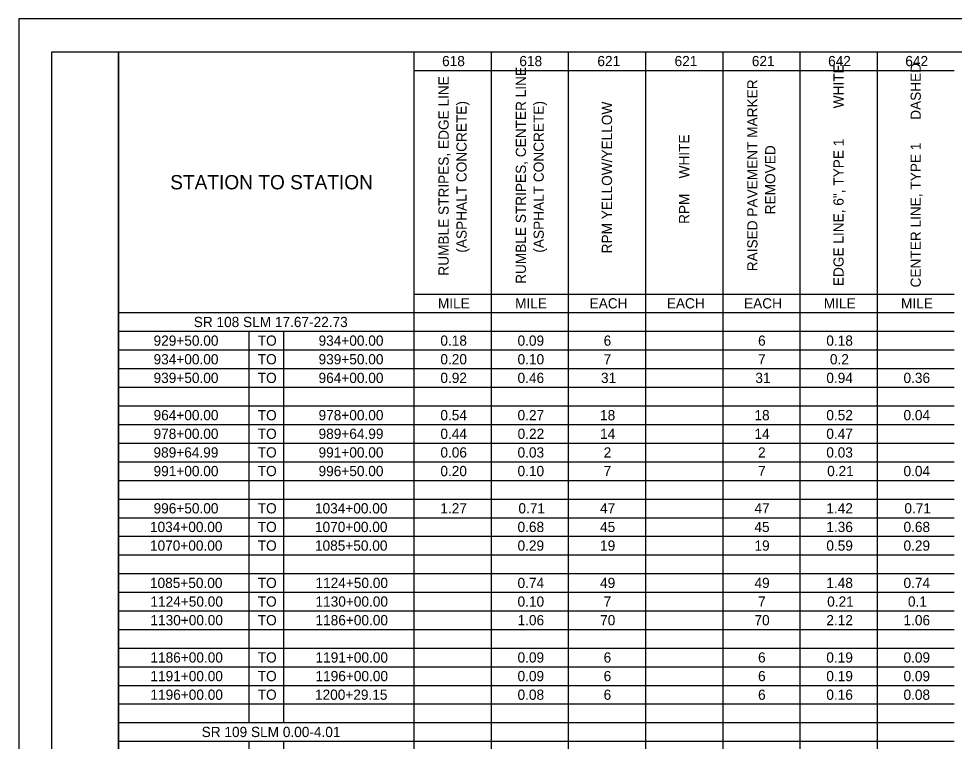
# Model space of a CAD drawing. Extents: x 0 to 34, y 0 to 22.
# Drawn here: x 0 to 14.06, y 11.14 to 22 of the extents above; entities that cross this region are included whole.
import ezdxf

# ---------------------------------------------------------------- set-up
doc = ezdxf.new("R2010")
doc.units = 0
for name, color, linetype in [('SH_Border', 7, 'Continuous'), ('SH_Cut_Line', 7, 'Continuous'), ('SH_Text', 7, 'Continuous')]:
    doc.layers.add(name, color=color, linetype=linetype)

msp = doc.modelspace()

# ---------------------------------------------------------------- linework, layer by layer
at = {"layer": 'SH_Border'}
for points in [[(0.5, 21.5), (1.5, 21.5), (1.5, 0.5), (0.5, 0.5)], [(1.5, 21.5), (33.5, 21.5), (33.5, 0.5), (1.5, 0.5)]]:
    msp.add_lwpolyline(points, close=True, dxfattribs=at)
at = {"layer": 'SH_Cut_Line'}
msp.add_lwpolyline([(0, 0), (34, 0), (34, 22), (0, 22)], close=True, dxfattribs=at)
at = {"layer": 'SH_Text'}
for p, q in [((1.5, 21.504), (3.02, 21.504)), ((1.5, 21.504), (1.5, 21.223)), ((3.02, 21.504), (14.062, 21.504)), ((5.941, 21.504), (5.941, 21.223)), ((7.101, 21.504), (7.101, 21.223)), ((8.261, 21.504), (8.261, 21.223)), ((9.421, 21.504), (9.421, 21.223)), ((10.582, 21.504), (10.582, 21.223)), ((11.742, 21.504), (11.742, 21.223)), ((12.902, 21.504), (12.902, 21.223)), ((1.5, 21.223), (1.5, 20.943)), ((5.941, 21.223), (14.062, 21.223)), ((5.941, 21.223), (5.941, 20.943)), ((7.101, 21.223), (7.101, 20.943)), ((8.261, 21.223), (8.261, 20.943)), ((9.421, 21.223), (9.421, 20.943)), ((10.582, 21.223), (10.582, 20.943)), ((11.742, 21.223), (11.742, 20.943)), ((12.902, 21.223), (12.902, 20.943)), ((1.5, 20.943), (1.5, 20.663)), ((5.941, 20.943), (5.941, 20.663)), ((7.101, 20.943), (7.101, 20.663)), ((8.261, 20.943), (8.261, 20.663)), ((9.421, 20.943), (9.421, 20.663)), ((10.582, 20.943), (10.582, 20.663)), ((11.742, 20.943), (11.742, 20.663)), ((12.902, 20.943), (12.902, 20.663)), ((1.5, 20.663), (1.5, 20.383)), ((5.941, 20.663), (5.941, 20.383)), ((7.101, 20.663), (7.101, 20.383)), ((8.261, 20.663), (8.261, 20.383)), ((9.421, 20.663), (9.421, 20.383)), ((10.582, 20.663), (10.582, 20.383)), ((11.742, 20.663), (11.742, 20.383)), ((12.902, 20.663), (12.902, 20.383)), ((1.5, 20.383), (1.5, 20.103)), ((5.941, 20.383), (5.941, 20.103)), ((7.101, 20.383), (7.101, 20.103)), ((8.261, 20.383), (8.261, 20.103)), ((9.421, 20.383), (9.421, 20.103)), ((10.582, 20.383), (10.582, 20.103)), ((11.742, 20.383), (11.742, 20.103)), ((12.902, 20.383), (12.902, 20.103)), ((1.5, 20.103), (1.5, 19.823)), ((5.941, 20.103), (5.941, 19.823)), ((7.101, 20.103), (7.101, 19.823)), ((8.261, 20.103), (8.261, 19.823)), ((9.421, 20.103), (9.421, 19.823)), ((10.582, 20.103), (10.582, 19.823)), ((11.742, 20.103), (11.742, 19.823)), ((12.902, 20.103), (12.902, 19.823)), ((1.5, 19.823), (1.5, 19.543)), ((5.941, 19.823), (5.941, 19.543)), ((7.101, 19.823), (7.101, 19.543)), ((8.261, 19.823), (8.261, 19.543)), ((9.421, 19.823), (9.421, 19.543)), ((10.582, 19.823), (10.582, 19.543)), ((11.742, 19.823), (11.742, 19.543)), ((12.902, 19.823), (12.902, 19.543)), ((1.5, 19.543), (1.5, 18.983)), ((5.941, 19.543), (5.941, 18.983)), ((7.101, 19.543), (7.101, 18.983)), ((8.261, 19.543), (8.261, 18.983)), ((9.421, 19.543), (9.421, 18.983)), ((10.582, 19.543), (10.582, 18.983)), ((11.742, 19.543), (11.742, 18.983)), ((12.902, 19.543), (12.902, 18.983)), ((1.5, 18.983), (1.5, 18.143)), ((5.941, 18.983), (5.941, 18.143)), ((7.101, 18.983), (7.101, 18.143)), ((8.261, 18.983), (8.261, 18.143)), ((9.421, 18.983), (9.421, 18.143)), ((10.582, 18.983), (10.582, 18.143)), ((11.742, 18.983), (11.742, 18.143)), ((12.902, 18.983), (12.902, 18.143)), ((1.5, 18.143), (1.5, 17.863)), ((5.941, 18.143), (5.941, 17.863)), ((7.101, 18.143), (7.101, 17.863)), ((8.261, 18.143), (8.261, 17.863)), ((9.421, 18.143), (9.421, 17.863)), ((10.582, 18.143), (10.582, 17.863)), ((11.742, 18.143), (11.742, 17.863)), ((12.902, 18.143), (12.902, 17.863)), ((1.5, 17.863), (1.5, 17.303)), ((5.941, 17.863), (14.062, 17.863)), ((5.941, 17.863), (5.941, 17.303)), ((7.101, 17.863), (7.101, 17.303)), ((8.261, 17.863), (8.261, 17.303)), ((9.421, 17.863), (9.421, 17.303)), ((10.582, 17.863), (10.582, 17.303)), ((11.742, 17.863), (11.742, 17.303)), ((12.902, 17.863), (12.902, 17.303)), ((1.5, 17.583), (3.02, 17.583)), ((3.02, 17.583), (14.062, 17.583)), ((1.5, 17.303), (3.02, 17.303)), ((1.5, 17.303), (1.5, 17.023)), ((3.02, 17.303), (14.062, 17.303)), ((3.46, 17.303), (3.46, 17.023)), ((3.98, 17.303), (3.98, 17.023)), ((5.941, 17.303), (5.941, 17.023)), ((7.101, 17.303), (7.101, 17.023)), ((8.261, 17.303), (8.261, 17.023)), ((9.421, 17.303), (9.421, 17.023)), ((10.582, 17.303), (10.582, 17.023)), ((11.742, 17.303), (11.742, 17.023)), ((12.902, 17.303), (12.902, 17.023)), ((1.5, 17.023), (3.02, 17.023)), ((1.5, 17.023), (1.5, 15.903)), ((3.02, 17.023), (14.062, 17.023)), ((3.46, 17.023), (3.46, 15.903)), ((3.98, 17.023), (3.98, 15.903)), ((5.941, 17.023), (5.941, 15.903)), ((7.101, 17.023), (7.101, 15.903)), ((8.261, 17.023), (8.261, 15.903)), ((9.421, 17.023), (9.421, 15.903)), ((10.582, 17.023), (10.582, 15.903)), ((11.742, 17.023), (11.742, 15.903)), ((12.902, 17.023), (12.902, 15.903)), ((1.5, 16.743), (3.02, 16.743)), ((3.02, 16.743), (14.062, 16.743)), ((1.5, 16.463), (3.02, 16.463)), ((3.02, 16.463), (14.062, 16.463)), ((1.5, 16.183), (3.02, 16.183)), ((3.02, 16.183), (14.062, 16.183)), ((1.5, 15.903), (3.02, 15.903)), ((1.5, 15.903), (1.5, 15.622)), ((3.02, 15.903), (14.062, 15.903)), ((3.46, 15.903), (3.46, 15.622)), ((3.98, 15.903), (3.98, 15.622)), ((5.941, 15.903), (5.941, 15.622)), ((7.101, 15.903), (7.101, 15.622)), ((8.261, 15.903), (8.261, 15.622)), ((9.421, 15.903), (9.421, 15.622)), ((10.582, 15.903), (10.582, 15.622)), ((11.742, 15.903), (11.742, 15.622)), ((12.902, 15.903), (12.902, 15.622)), ((1.5, 15.622), (3.02, 15.622)), ((1.5, 15.622), (1.5, 15.062)), ((3.02, 15.622), (14.062, 15.622)), ((3.46, 15.622), (3.46, 15.062)), ((3.98, 15.622), (3.98, 15.062)), ((5.941, 15.622), (5.941, 15.062)), ((7.101, 15.622), (7.101, 15.062)), ((8.261, 15.622), (8.261, 15.062)), ((9.421, 15.622), (9.421, 15.062)), ((10.582, 15.622), (10.582, 15.062)), ((11.742, 15.622), (11.742, 15.062)), ((12.902, 15.622), (12.902, 15.062)), ((1.5, 15.342), (3.02, 15.342)), ((3.02, 15.342), (14.062, 15.342)), ((1.5, 15.062), (3.02, 15.062)), ((1.5, 15.062), (1.5, 14.502)), ((3.02, 15.062), (14.062, 15.062)), ((3.46, 15.062), (3.46, 14.502)), ((3.98, 15.062), (3.98, 14.502)), ((5.941, 15.062), (5.941, 14.502)), ((7.101, 15.062), (7.101, 14.502)), ((8.261, 15.062), (8.261, 14.502)), ((9.421, 15.062), (9.421, 14.502)), ((10.582, 15.062), (10.582, 14.502)), ((11.742, 15.062), (11.742, 14.502)), ((12.902, 15.062), (12.902, 14.502)), ((1.5, 14.782), (3.02, 14.782)), ((3.02, 14.782), (14.062, 14.782)), ((1.5, 14.502), (3.02, 14.502)), ((1.5, 14.502), (1.5, 14.222)), ((3.02, 14.502), (14.062, 14.502)), ((3.46, 14.502), (3.46, 14.222)), ((3.98, 14.502), (3.98, 14.222)), ((5.941, 14.502), (5.941, 14.222)), ((7.101, 14.502), (7.101, 14.222)), ((8.261, 14.502), (8.261, 14.222)), ((9.421, 14.502), (9.421, 14.222)), ((10.582, 14.502), (10.582, 14.222)), ((11.742, 14.502), (11.742, 14.222)), ((12.902, 14.502), (12.902, 14.222)), ((1.5, 14.222), (3.02, 14.222)), ((1.5, 14.222), (1.5, 13.662)), ((3.02, 14.222), (14.062, 14.222)), ((3.46, 14.222), (3.46, 13.662)), ((3.98, 14.222), (3.98, 13.662)), ((5.941, 14.222), (5.941, 13.662)), ((7.101, 14.222), (7.101, 13.662)), ((8.261, 14.222), (8.261, 13.662)), ((9.421, 14.222), (9.421, 13.662)), ((10.582, 14.222), (10.582, 13.662)), ((11.742, 14.222), (11.742, 13.662)), ((12.902, 14.222), (12.902, 13.662)), ((1.5, 13.942), (3.02, 13.942)), ((3.02, 13.942), (14.062, 13.942)), ((1.5, 13.662), (3.02, 13.662)), ((1.5, 13.662), (1.5, 13.382)), ((3.02, 13.662), (14.062, 13.662)), ((3.46, 13.662), (3.46, 13.382)), ((3.98, 13.662), (3.98, 13.382)), ((5.941, 13.662), (5.941, 13.382)), ((7.101, 13.662), (7.101, 13.382)), ((8.261, 13.662), (8.261, 13.382)), ((9.421, 13.662), (9.421, 13.382)), ((10.582, 13.662), (10.582, 13.382)), ((11.742, 13.662), (11.742, 13.382)), ((12.902, 13.662), (12.902, 13.382)), ((1.5, 13.382), (3.02, 13.382)), ((1.5, 13.382), (1.5, 12.542)), ((3.02, 13.382), (14.062, 13.382)), ((3.46, 13.382), (3.46, 12.542)), ((3.98, 13.382), (3.98, 12.542)), ((5.941, 13.382), (5.941, 12.542)), ((7.101, 13.382), (7.101, 12.542)), ((8.261, 13.382), (8.261, 12.542)), ((9.421, 13.382), (9.421, 12.542)), ((10.582, 13.382), (10.582, 12.542)), ((11.742, 13.382), (11.742, 12.542)), ((12.902, 13.382), (12.902, 12.542)), ((1.5, 13.102), (3.02, 13.102)), ((3.02, 13.102), (14.062, 13.102)), ((1.5, 12.822), (3.02, 12.822)), ((3.02, 12.822), (14.062, 12.822)), ((1.5, 12.542), (3.02, 12.542)), ((1.5, 12.542), (1.5, 11.982)), ((3.02, 12.542), (14.062, 12.542)), ((3.46, 12.542), (3.46, 11.982)), ((3.98, 12.542), (3.98, 11.982)), ((5.941, 12.542), (5.941, 11.982)), ((7.101, 12.542), (7.101, 11.982)), ((8.261, 12.542), (8.261, 11.982)), ((9.421, 12.542), (9.421, 11.982)), ((10.582, 12.542), (10.582, 11.982)), ((11.742, 12.542), (11.742, 11.982)), ((12.902, 12.542), (12.902, 11.982)), ((1.5, 12.262), (3.02, 12.262)), ((3.02, 12.262), (14.062, 12.262)), ((1.5, 11.982), (3.02, 11.982)), ((1.5, 11.982), (1.5, 11.142)), ((3.02, 11.982), (14.062, 11.982)), ((3.46, 11.982), (3.46, 11.422)), ((3.98, 11.982), (3.98, 11.422)), ((5.941, 11.982), (5.941, 11.142)), ((7.101, 11.982), (7.101, 11.142)), ((8.261, 11.982), (8.261, 11.142)), ((9.421, 11.982), (9.421, 11.142)), ((10.582, 11.982), (10.582, 11.142)), ((11.742, 11.982), (11.742, 11.142)), ((12.902, 11.982), (12.902, 11.142)), ((1.5, 11.702), (3.02, 11.702)), ((3.02, 11.702), (14.062, 11.702)), ((1.5, 11.422), (3.02, 11.422)), ((3.02, 11.422), (14.062, 11.422)), ((1.5, 11.142), (3.02, 11.142)), ((1.5, 11.142), (1.5, 10.582)), ((3.02, 11.142), (14.062, 11.142)), ((3.46, 11.142), (3.46, 10.582)), ((3.98, 11.142), (3.98, 10.582)), ((5.941, 11.142), (5.941, 10.582)), ((7.101, 11.142), (7.101, 10.582)), ((8.261, 11.142), (8.261, 10.582)), ((9.421, 11.142), (9.421, 10.582)), ((10.582, 11.142), (10.582, 10.582)), ((11.742, 11.142), (11.742, 10.582)), ((12.902, 11.142), (12.902, 10.582))]:
    msp.add_line(p, q, dxfattribs=at)

# ---------------------------------------------------------------- texts
for s, height, p in [('618', 0.1534, (6.364, 21.287)), ('618', 0.1534, (7.525, 21.287)), ('621', 0.1534, (8.698, 21.287)), ('621', 0.1534, (9.858, 21.287)), ('621', 0.1534, (11.019, 21.287)), ('642', 0.1534, (12.166, 21.287)), ('642', 0.1534, (13.326, 21.287)), ('STATION TO STATION', 0.21471, (2.277, 19.436)), ('MILE', 0.1534, (6.301, 17.646)), ('MILE', 0.1534, (7.461, 17.646)), ('EACH', 0.1534, (8.581, 17.646)), ('EACH', 0.1534, (9.741, 17.646)), ('EACH', 0.1534, (10.902, 17.646)), ('MILE', 0.1534, (12.102, 17.646)), ('MILE', 0.1534, (13.262, 17.646)), ('SR 108 SLM 17.67-22.73', 0.15336, (2.631, 17.366)), ('929+50.00', 0.1534, (2.027, 17.086)), ('TO', 0.1534, (3.593, 17.086)), ('934+00.00', 0.1534, (4.507, 17.086)), ('0.18', 0.1534, (6.338, 17.086)), ('0.09', 0.1534, (7.498, 17.086)), ('6', 0.153, (8.792, 17.086)), ('6', 0.153, (11.113, 17.086)), ('0.18', 0.1534, (12.139, 17.086)), ('934+00.00', 0.1534, (2.027, 16.806)), ('TO', 0.1534, (3.593, 16.806)), ('939+50.00', 0.1534, (4.507, 16.806)), ('0.20', 0.1534, (6.338, 16.806)), ('0.10', 0.1534, (7.498, 16.806)), ('7', 0.153, (8.792, 16.806)), ('7', 0.153, (11.113, 16.806)), ('0.2', 0.1534, (12.193, 16.806)), ('939+50.00', 0.1534, (2.027, 16.526)), ('TO', 0.1534, (3.593, 16.526)), ('964+00.00', 0.1534, (4.507, 16.526)), ('0.92', 0.1534, (6.338, 16.526)), ('0.46', 0.1534, (7.498, 16.526)), ('31', 0.1534, (8.752, 16.526)), ('31', 0.1534, (11.072, 16.526)), ('0.94', 0.1534, (12.139, 16.526)), ('0.36', 0.1534, (13.299, 16.526)), ('964+00.00', 0.1534, (2.027, 15.966)), ('TO', 0.1534, (3.593, 15.966)), ('978+00.00', 0.1534, (4.507, 15.966)), ('0.54', 0.1534, (6.338, 15.966)), ('0.27', 0.1534, (7.498, 15.966)), ('18', 0.1534, (8.738, 15.966)), ('18', 0.1534, (11.059, 15.966)), ('0.52', 0.1534, (12.139, 15.966)), ('0.04', 0.1534, (13.299, 15.966)), ('978+00.00', 0.1534, (2.027, 15.686)), ('TO', 0.1534, (3.593, 15.686)), ('989+64.99', 0.1534, (4.507, 15.686)), ('0.44', 0.1534, (6.338, 15.686)), ('0.22', 0.1534, (7.499, 15.686)), ('14', 0.1534, (8.739, 15.686)), ('14', 0.1534, (11.059, 15.686)), ('0.47', 0.1534, (12.139, 15.686)), ('989+64.99', 0.1534, (2.026, 15.406)), ('TO', 0.1534, (3.593, 15.406)), ('991+00.00', 0.1534, (4.507, 15.406)), ('0.06', 0.1534, (6.338, 15.406)), ('0.03', 0.1534, (7.498, 15.406)), ('2', 0.153, (8.793, 15.406)), ('2', 0.153, (11.113, 15.406)), ('0.03', 0.1534, (12.139, 15.406)), ('991+00.00', 0.1534, (2.027, 15.126)), ('TO', 0.1534, (3.593, 15.126)), ('996+50.00', 0.1534, (4.507, 15.126)), ('0.20', 0.1534, (6.338, 15.126)), ('0.10', 0.1534, (7.498, 15.126)), ('7', 0.153, (8.792, 15.126)), ('7', 0.153, (11.113, 15.126)), ('0.21', 0.1534, (12.152, 15.126)), ('0.04', 0.1534, (13.299, 15.126)), ('996+50.00', 0.1534, (2.027, 14.566)), ('TO', 0.1534, (3.593, 14.566)), ('1034+00.00', 0.1534, (4.453, 14.566)), ('1.27', 0.1534, (6.338, 14.566)), ('0.71', 0.1534, (7.511, 14.566)), ('47', 0.1534, (8.738, 14.566)), ('47', 0.1534, (11.059, 14.566)), ('1.42', 0.1534, (12.139, 14.566)), ('0.71', 0.1534, (13.312, 14.566)), ('1034+00.00', 0.1534, (1.973, 14.286)), ('TO', 0.1534, (3.593, 14.286)), ('1070+00.00', 0.1534, (4.453, 14.286)), ('0.68', 0.1534, (7.498, 14.286)), ('45', 0.1534, (8.738, 14.286)), ('45', 0.1534, (11.058, 14.286)), ('1.36', 0.1534, (12.139, 14.286)), ('0.68', 0.1534, (13.299, 14.286)), ('1070+00.00', 0.1534, (1.973, 14.006)), ('TO', 0.1534, (3.593, 14.006)), ('1085+50.00', 0.1534, (4.453, 14.006)), ('0.29', 0.1534, (7.498, 14.006)), ('19', 0.1534, (8.738, 14.006)), ('19', 0.1534, (11.059, 14.006)), ('0.59', 0.1534, (12.139, 14.006)), ('0.29', 0.1534, (13.299, 14.006)), ('1085+50.00', 0.1534, (1.973, 13.445)), ('TO', 0.1534, (3.593, 13.445)), ('1124+50.00', 0.1534, (4.461, 13.445)), ('0.74', 0.1534, (7.498, 13.445)), ('49', 0.1534, (8.738, 13.445)), ('49', 0.1534, (11.059, 13.445)), ('1.48', 0.1534, (12.139, 13.445)), ('0.74', 0.1534, (13.299, 13.445)), ('1124+50.00', 0.1534, (1.98, 13.165)), ('TO', 0.1534, (3.593, 13.165)), ('1130+00.00', 0.1534, (4.461, 13.165)), ('0.10', 0.1534, (7.498, 13.165)), ('7', 0.153, (8.792, 13.165)), ('7', 0.153, (11.113, 13.165)), ('0.21', 0.1534, (12.152, 13.165)), ('0.1', 0.1534, (13.366, 13.165)), ('1130+00.00', 0.1534, (1.98, 12.885)), ('TO', 0.1534, (3.593, 12.885)), ('1186+00.00', 0.1534, (4.461, 12.885)), ('1.06', 0.1534, (7.498, 12.885)), ('70', 0.1534, (8.739, 12.885)), ('70', 0.1534, (11.059, 12.885)), ('2.12', 0.1534, (12.139, 12.885)), ('1.06', 0.1534, (13.299, 12.885)), ('1186+00.00', 0.1534, (1.98, 12.325)), ('TO', 0.1534, (3.593, 12.325)), ('1191+00.00', 0.1534, (4.461, 12.325)), ('0.09', 0.1534, (7.498, 12.325)), ('6', 0.153, (8.792, 12.325)), ('6', 0.153, (11.113, 12.325)), ('0.19', 0.1534, (12.139, 12.325)), ('0.09', 0.1534, (13.299, 12.325)), ('1191+00.00', 0.1534, (1.98, 12.045)), ('TO', 0.1534, (3.593, 12.045)), ('1196+00.00', 0.1534, (4.461, 12.045)), ('0.09', 0.1534, (7.498, 12.045)), ('6', 0.153, (8.792, 12.045)), ('6', 0.153, (11.113, 12.045)), ('0.19', 0.1534, (12.139, 12.045)), ('0.09', 0.1534, (13.299, 12.045)), ('1196+00.00', 0.1534, (1.98, 11.765)), ('TO', 0.1534, (3.593, 11.765)), ('1200+29.15', 0.1534, (4.453, 11.765)), ('0.08', 0.1534, (7.498, 11.765)), ('6', 0.153, (8.792, 11.765)), ('6', 0.153, (11.113, 11.765)), ('0.16', 0.1534, (12.139, 11.765)), ('0.08', 0.1534, (13.299, 11.765)), ('SR 109 SLM 0.00-4.01', 0.15336, (2.75, 11.205))]:
    msp.add_text(s, height=height, dxfattribs=at).set_placement(p)
for s, height, p in [('RUMBLE STRIPES, CENTER LINE ', 0.15336, (7.624, 18.016)), ('EDGE LINE, 6", TYPE 1        WHITE', 0.15336, (12.399, 17.982)), ('CENTER LINE, TYPE 1      DASHED', 0.15336, (13.559, 17.962)), ('RUMBLE STRIPES, EDGE LINE ', 0.15336, (6.463, 18.139)), ('RAISED PAVEMENT MARKER ', 0.15336, (11.104, 18.205)), ('(ASPHALT CONCRETE)', 0.15336, (6.732, 18.484)), ('(ASPHALT CONCRETE)', 0.15336, (7.892, 18.484)), ('RPM YELLOW/YELLOW', 0.15336, (8.918, 18.474)), ('RPM    WHITE', 0.15336, (10.078, 18.916)), ('REMOVED', 0.1534, (11.373, 19.061))]:
    msp.add_text(s, height=height, rotation=90, dxfattribs=at).set_placement(p)

doc.saveas('drawing.dxf')
